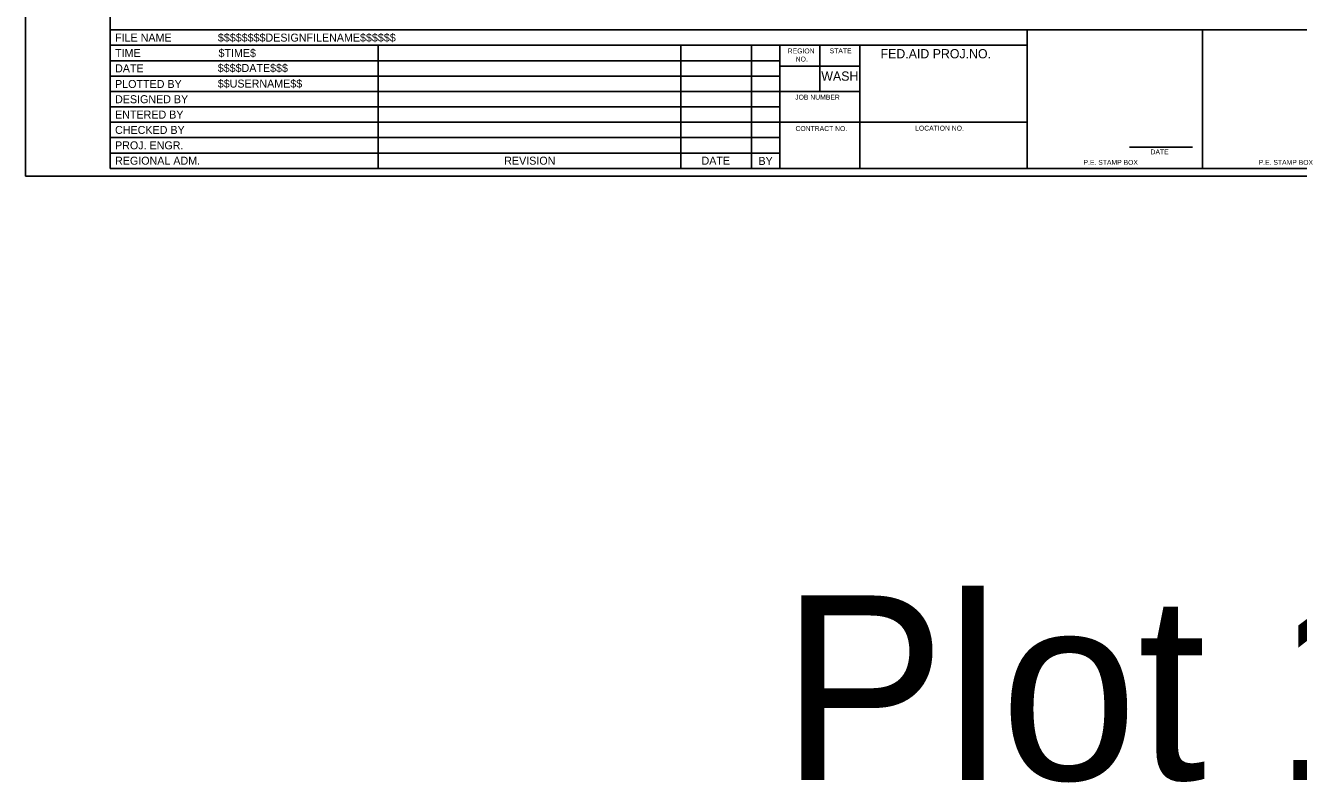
# Model space of a CAD drawing. Extents: x 99988 to 100172, y 99995 to 100047.
# Drawn here: x 99999.31 to 100009.66, y 99995.01 to 100001.16 of the extents above; entities that cross this region are included whole.
import ezdxf

# ---------------------------------------------------------------- set-up
doc = ezdxf.new("R2010")
doc.units = 0
for name, color, linetype in [('SH_GI_PlotLimits', 7, 'Continuous'), ('SH_GI_SheetBorder', 7, 'Continuous'), ('SH_GI_SheetLocationText', 7, 'Continuous'), ('SH_GI_SheetTextInCells', 7, 'Continuous'), ('SH_GI_TitleBlockText', 7, 'Continuous')]:
    doc.layers.add(name, color=color, linetype=linetype)

msp = doc.modelspace()

# ---------------------------------------------------------------- linework, layer by layer
at = {"layer": 'SH_GI_PlotLimits'}
msp.add_lwpolyline([(99999.312, 99999.937), (100015.812, 99999.937), (100015.812, 100010.437), (99999.312, 100010.437)], close=True, dxfattribs=at)
at = {"layer": 'SH_GI_SheetBorder'}
for p, q in [((100000, 100010.375), (100000, 100000)), ((100000, 100001.126), (100015.75, 100001.126)), ((100007.457, 100000), (100007.457, 100001.126)), ((100008.883, 100000), (100008.883, 100001.126)), ((100000, 100001.001), (100007.457, 100001.001)), ((100002.179, 100001.001), (100002.179, 100000)), ((100004.641, 100001.001), (100004.641, 100000)), ((100005.216, 100001.001), (100005.216, 100000)), ((100005.445, 100001.001), (100005.445, 100000)), ((100005.772, 100000.625), (100005.772, 100001.001)), ((100006.096, 100000), (100006.096, 100001.001)), ((100000, 100000.876), (100002.182, 100000.876)), ((100002.182, 100000.876), (100005.447, 100000.876)), ((100006.096, 100000.831), (100005.447, 100000.831)), ((100000, 100000.751), (100002.182, 100000.751)), ((100002.182, 100000.751), (100005.447, 100000.751)), ((100000, 100000.625), (100005.447, 100000.625)), ((100006.096, 100000.625), (100005.447, 100000.625)), ((100000, 100000.5), (100005.447, 100000.5)), ((100000, 100000.375), (100005.447, 100000.375)), ((100007.457, 100000.375), (100005.447, 100000.375)), ((100000, 100000.25), (100005.447, 100000.25)), ((100008.29, 100000.173), (100008.802, 100000.173)), ((100000, 100000.125), (100005.447, 100000.125)), ((100000, 100000), (100015.75, 100000))]:
    msp.add_line(p, q, dxfattribs=at)

# ---------------------------------------------------------------- texts
at = {"layer": 'SH_GI_SheetLocationText'}
msp.add_text('Plot 1', height=1.5, dxfattribs=at).set_placement((100005.455, 99995.027))
at = {"layer": 'SH_GI_SheetTextInCells'}
for s, height, p in [('FILE NAME', 0.0651, (100000.041, 100001.031)), ('TIME', 0.0651, (100000.041, 100000.906)), ('REGION', 0.04, (100005.51, 100000.935)), ('NO.', 0.04, (100005.575, 100000.869)), ('STATE', 0.04, (100005.851, 100000.936)), ('FED.AID PROJ.NO.', 0.07506, (100006.265, 100000.895)), ('DATE', 0.0651, (100000.041, 100000.781)), ('PLOTTED BY', 0.0651, (100000.041, 100000.654)), ('WASH', 0.0751, (100005.783, 100000.713)), ('DESIGNED BY', 0.06505, (100000.041, 100000.53)), ('JOB NUMBER', 0.04, (100005.571, 100000.559)), ('ENTERED BY', 0.0651, (100000.041, 100000.405)), ('CHECKED BY', 0.0651, (100000.041, 100000.28)), ('CONTRACT NO.', 0.04003, (100005.573, 100000.304)), ('LOCATION NO.', 0.04003, (100006.546, 100000.307)), ('PROJ. ENGR.', 0.06505, (100000.041, 100000.155)), ('REGIONAL ADM.', 0.06505, (100000.041, 100000.03)), ('REVISION', 0.0651, (100003.205, 100000.03)), ('DATE', 0.0651, (100004.809, 100000.03)), ('BY', 0.0651, (100005.272, 100000.028)), ('P.E. STAMP BOX', 0.04003, (100007.915, 100000.029)), ('DATE', 0.04, (100008.46, 100000.114)), ('P.E. STAMP BOX', 0.04003, (100009.339, 100000.029))]:
    msp.add_text(s, height=height, dxfattribs=at).set_placement(p)
at = {"layer": 'SH_GI_TitleBlockText'}
for s, height, p in [('$$$$$$$$DESIGNFILENAME$$$$$$', 0.06505, (100000.877, 100001.031)), ('$TIME$', 0.0651, (100000.882, 100000.906)), ('$$$$DATE$$$', 0.06505, (100000.876, 100000.784)), ('$$USERNAME$$', 0.06505, (100000.876, 100000.657))]:
    msp.add_text(s, height=height, dxfattribs=at).set_placement(p)

doc.saveas('drawing.dxf')
